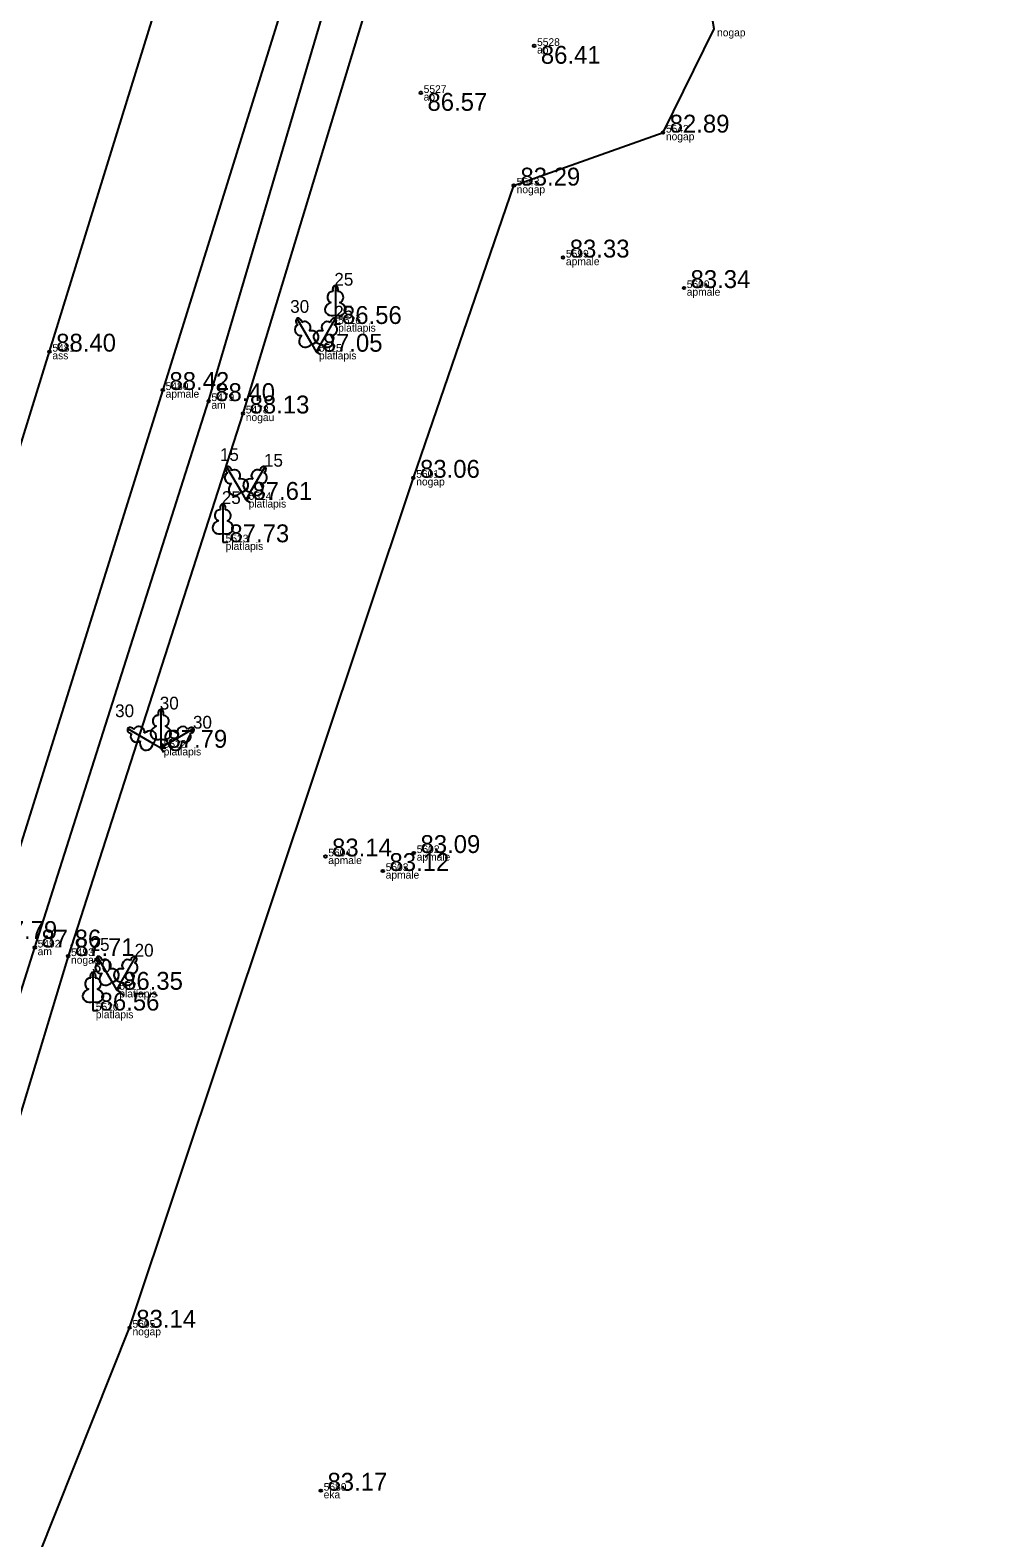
# Model space of a CAD drawing. Extents: x 614911 to 615803, y 262110 to 264311.
# Drawn here: x 615597 to 615634.5, y 262876.1 to 262935.1 of the extents above; entities that cross this region are included whole.
import ezdxf

# ---------------------------------------------------------------- set-up
doc = ezdxf.new("R2010")
doc.units = 0
for name, color, linetype in [('Level 1', 7, 'Continuous'), ('Level 31', 7, 'Continuous'), ('Level 37', 7, 'Continuous'), ('Level 53', 7, 'Continuous'), ('Level 54', 7, 'Continuous'), ('Level 57', 7, 'Continuous'), ('Level 58', 7, 'Continuous')]:
    doc.layers.add(name, color=color, linetype=linetype)

msp = doc.modelspace()

# ---------------------------------------------------------------- linework, layer by layer
at = {"layer": 'Level 1'}
for p, q in [((615608.989, 262923.95), (615608.989, 262923.603)), ((615608.989, 262923.603), (615609.189, 262923.603)), ((615608.062, 262922.817), (615608.235, 262922.516)), ((615608.408, 262922.817), (615608.235, 262922.516)), ((615608.235, 262922.516), (615608.408, 262922.616)), ((615608.235, 262922.516), (615608.408, 262922.416)), ((615605.308, 262917.015), (615605.481, 262916.714)), ((615605.654, 262917.015), (615605.481, 262916.714)), ((615605.481, 262916.714), (615605.654, 262916.814)), ((615605.481, 262916.714), (615605.654, 262916.614)), ((615604.58, 262915.399), (615604.58, 262915.052)), ((615604.58, 262915.052), (615604.78, 262915.052)), ((615601.85, 262907.176), (615602.151, 262907.003)), ((615602.151, 262907.35), (615602.151, 262907.003)), ((615602.151, 262907.003), (615602.251, 262907.176)), ((615602.452, 262907.176), (615602.151, 262907.003)), ((615602.151, 262907.003), (615602.351, 262907.003)), ((615602.151, 262907.003), (615602.251, 262906.83)), ((615600.242, 262897.825), (615600.415, 262897.524)), ((615600.588, 262897.825), (615600.415, 262897.524)), ((615600.415, 262897.524), (615600.588, 262897.624)), ((615600.415, 262897.524), (615600.588, 262897.424)), ((615599.495, 262897.056), (615599.495, 262896.709)), ((615599.495, 262896.709), (615599.695, 262896.709))]:
    msp.add_line(p, q, dxfattribs=at)
for points in [[(615608.989, 262925.103), (615608.989, 262923.95)], [(615609.079, 262924.871), (615609.078, 262924.872)], [(615607.485, 262923.815), (615608.062, 262922.817)], [(615607.679, 262923.659), (615607.677, 262923.659)], [(615608.985, 262923.815), (615608.408, 262922.817)], [(615608.946, 262923.569), (615608.946, 262923.57)], [(615604.731, 262918.013), (615605.308, 262917.015)], [(615604.925, 262917.857), (615604.923, 262917.857)], [(615606.231, 262918.013), (615605.654, 262917.015)], [(615606.192, 262917.767), (615606.192, 262917.768)], [(615604.58, 262916.552), (615604.58, 262915.399)], [(615604.67, 262916.32), (615604.669, 262916.321)], [(615602.151, 262908.503), (615602.151, 262907.35)], [(615602.241, 262908.271), (615602.24, 262908.272)], [(615600.852, 262907.753), (615601.85, 262907.176)], [(615601.098, 262907.714), (615601.097, 262907.714)], [(615603.45, 262907.753), (615602.452, 262907.176)], [(615603.294, 262907.559), (615603.294, 262907.561)], [(615599.665, 262898.823), (615600.242, 262897.825)], [(615599.859, 262898.667), (615599.857, 262898.667)], [(615601.165, 262898.823), (615600.588, 262897.825)], [(615599.495, 262898.209), (615599.495, 262897.056)], [(615601.126, 262898.577), (615601.126, 262898.578)], [(615599.585, 262897.977), (615599.584, 262897.978)]]:
    msp.add_lwpolyline(points, dxfattribs=at)
for centre, major_axis, ratio, start_param, end_param in [((615608.861, 262924.658), (-0.039, -0.212), 0.861323, 3.141593, 6.283185), ((615608.989, 262924.953), (0, -0.15), 0.707107, 3.14537, 5.287485), ((615608.989, 262924.953), (0, -0.15), 0.707107, 0.995701, 3.137816), ((615609.117, 262924.658), (0.039, -0.212), 0.861323, 0, 3.141593), ((615608.899, 262924.196), (0.307, 0.095), 0.814445, 1.570796, 4.752015), ((615609.079, 262924.196), (-0.307, 0.095), 0.814445, 1.531171, 4.712389), ((615607.596, 262923.366), (0.073, -0.203), 0.861323, 3.141593, 6.283185), ((615607.56, 262923.685), (0.075, -0.13), 0.707107, 3.14537, 5.287485), ((615607.56, 262923.685), (0.075, -0.13), 0.707107, 0.995701, 3.137816), ((615607.819, 262923.494), (0.14, -0.165), 0.861323, 0, 3.141593), ((615608.651, 262923.494), (-0.14, -0.165), 0.861323, 3.141593, 6.283185), ((615608.91, 262923.685), (-0.075, -0.13), 0.707107, 3.14537, 5.287485), ((615608.874, 262923.366), (-0.073, -0.203), 0.861323, 0, 3.141593), ((615608.91, 262923.685), (-0.075, -0.13), 0.707107, 0.995701, 3.137816), ((615607.861, 262922.985), (0.218, 0.236), 0.814445, 1.570796, 4.752015), ((615608.016, 262923.074), (-0.313, -0.071), 0.814445, 1.531171, 4.712389), ((615608.454, 262923.074), (0.313, -0.071), 0.814445, 1.570796, 4.752015), ((615608.609, 262922.985), (-0.218, 0.236), 0.814445, 1.531171, 4.712389), ((615604.842, 262917.564), (0.073, -0.203), 0.861323, 3.141593, 6.283185), ((615604.806, 262917.883), (0.075, -0.13), 0.707107, 3.14537, 5.287485), ((615604.806, 262917.883), (0.075, -0.13), 0.707107, 0.995701, 3.137816), ((615605.065, 262917.692), (0.14, -0.165), 0.861323, 0, 3.141593), ((615605.262, 262917.272), (-0.313, -0.071), 0.814445, 1.531171, 4.712389), ((615605.7, 262917.272), (0.313, -0.071), 0.814445, 1.570796, 4.752015), ((615605.897, 262917.692), (-0.14, -0.165), 0.861323, 3.141593, 6.283185), ((615606.156, 262917.883), (-0.075, -0.13), 0.707107, 3.14537, 5.287485), ((615606.12, 262917.564), (-0.073, -0.203), 0.861323, 0, 3.141593), ((615606.156, 262917.883), (-0.075, -0.13), 0.707107, 0.995701, 3.137816), ((615605.107, 262917.183), (0.218, 0.236), 0.814445, 1.570796, 4.752015), ((615605.855, 262917.183), (-0.218, 0.236), 0.814445, 1.531171, 4.712389), ((615604.452, 262916.107), (-0.039, -0.212), 0.861323, 3.141593, 6.283185), ((615604.58, 262916.402), (0, -0.15), 0.707107, 3.14537, 5.287485), ((615604.58, 262916.402), (0, -0.15), 0.707107, 0.995701, 3.137816), ((615604.708, 262916.107), (0.039, -0.212), 0.861323, 0, 3.141593), ((615604.49, 262915.645), (0.307, 0.095), 0.814445, 1.570796, 4.752015), ((615604.67, 262915.645), (-0.307, 0.095), 0.814445, 1.531171, 4.712389), ((615602.023, 262908.058), (-0.039, -0.212), 0.861323, 3.141593, 6.283185), ((615602.151, 262908.353), (0, -0.15), 0.707107, 3.14537, 5.287485), ((615602.151, 262908.353), (0, -0.15), 0.707107, 0.995701, 3.137816), ((615602.279, 262908.058), (0.039, -0.212), 0.861323, 0, 3.141593), ((615600.982, 262907.678), (0.13, -0.075), 0.707107, 3.14537, 5.287485), ((615600.982, 262907.678), (0.13, -0.075), 0.707107, 0.995701, 3.137816), ((615601.173, 262907.419), (0.165, -0.14), 0.861323, 3.141593, 6.283185), ((615601.301, 262907.642), (0.203, -0.073), 0.861323, 0, 3.141593), ((615601.682, 262907.377), (-0.236, -0.218), 0.814445, 1.531171, 4.712389), ((615602.061, 262907.596), (0.307, 0.095), 0.814445, 1.570796, 4.752015), ((615602.241, 262907.596), (-0.307, 0.095), 0.814445, 1.531171, 4.712389), ((615602.62, 262907.377), (0.236, -0.218), 0.814445, 1.570796, 4.752015), ((615603.001, 262907.642), (-0.203, -0.073), 0.861323, 3.141593, 6.283185), ((615603.129, 262907.419), (-0.165, -0.14), 0.861323, 0, 3.141593), ((615603.32, 262907.678), (-0.13, -0.075), 0.707107, 3.14537, 5.287485), ((615603.32, 262907.678), (-0.13, -0.075), 0.707107, 0.995701, 3.137816), ((615601.593, 262907.222), (0.071, 0.313), 0.814445, 1.570796, 4.752015), ((615602.709, 262907.222), (-0.071, 0.313), 0.814445, 1.531171, 4.712389), ((615599.74, 262898.693), (0.075, -0.13), 0.707107, 3.14537, 5.287485), ((615599.74, 262898.693), (0.075, -0.13), 0.707107, 0.995701, 3.137816), ((615599.999, 262898.502), (0.14, -0.165), 0.861323, 0, 3.141593), ((615600.831, 262898.502), (-0.14, -0.165), 0.861323, 3.141593, 6.283185), ((615601.09, 262898.693), (-0.075, -0.13), 0.707107, 3.14537, 5.287485), ((615601.09, 262898.693), (-0.075, -0.13), 0.707107, 0.995701, 3.137816), ((615599.495, 262898.059), (0, -0.15), 0.707107, 3.14537, 5.287485), ((615599.495, 262898.059), (0, -0.15), 0.707107, 0.995701, 3.137816), ((615599.776, 262898.374), (0.073, -0.203), 0.861323, 3.141593, 6.283185), ((615600.041, 262897.993), (0.218, 0.236), 0.814445, 1.570796, 4.752015), ((615600.196, 262898.082), (-0.313, -0.071), 0.814445, 1.531171, 4.712389), ((615600.634, 262898.082), (0.313, -0.071), 0.814445, 1.570796, 4.752015), ((615600.789, 262897.993), (-0.218, 0.236), 0.814445, 1.531171, 4.712389), ((615601.054, 262898.374), (-0.073, -0.203), 0.861323, 0, 3.141593), ((615599.405, 262897.302), (0.307, 0.095), 0.814445, 1.570796, 4.752015), ((615599.367, 262897.764), (-0.039, -0.212), 0.861323, 3.141593, 6.283185), ((615599.585, 262897.302), (-0.307, 0.095), 0.814445, 1.531171, 4.712389), ((615599.623, 262897.764), (0.039, -0.212), 0.861323, 0, 3.141593)]:
    msp.add_ellipse(centre, major_axis=major_axis, ratio=ratio, start_param=start_param, end_param=end_param, dxfattribs=at)
at = {"layer": 'Level 31'}
for points in [[(615632.734, 262974.874), (615627.762, 262975.783), (615624.583, 262974.081), (615622.329, 262970.726), (615619.288, 262963.641), (615611.976, 262941.852), (615605.37, 262920.098), (615598.524, 262898.844), (615592.115, 262877.692), (615586.071, 262858.355), (615583.42, 262849.533), (615582.048, 262845.554), (615581.571, 262838.931), (615579.909, 262826.022), (615579.783, 262825.588), (615576.605, 262812.081)], [(615581.33, 262813.385), (615587.235, 262840.341), (615585.874, 262843.893), (615588.538, 262850.225), (615593.068, 262864.597), (615600.932, 262884.287), (615612.047, 262917.578), (615615.98, 262929.024), (615621.827, 262931.099), (615623.831, 262935.169), (615622.903, 262940.536), (615628.682, 262961.888), (615634.511, 262966.199), (615634.511, 262966.199)]]:
    msp.add_lwpolyline(points, dxfattribs=at)
at = {"layer": 'Level 37'}
for points in [[(615552.83, 262775.419), (615557.688, 262792.217), (615564.381, 262810.929), (615568.874, 262829.598), (615578.474, 262860.105), (615584.765, 262880.506), (615591.133, 262901.009), (615597.793, 262922.52), (615604.506, 262944.221), (615611.821, 262967.016), (615619.311, 262990.31), (615624.144, 263005.661), (615628.856, 263023.992)], [(615633.153, 262995.478), (615630.105, 262994.778), (615627.249, 262993.097), (615624.165, 262989.775), (615623.012, 262986.721), (615615.941, 262964.659), (615608.941, 262942.572), (615602.23, 262921.018), (615595.493, 262899.514), (615589.041, 262878.574), (615583.023, 262859.136), (615579.804, 262848.845), (615577.579, 262826.156), (615572.51, 262808.384), (615566.84, 262788.492), (615562.353, 262772.755), (615562.228, 262772.268), (615562.322, 262770.686), (615563.546, 262768.507), (615565.703, 262767.319), (615569.868, 262766.432), (615584.992, 262762.796)], [(615576.19, 262811.993), (615576.066, 262812.682), (615575.818, 262813.59), (615579.291, 262825.832), (615581.523, 262848.494), (615584.551, 262858.603), (615590.575, 262878.181), (615597.215, 262899.18), (615604.023, 262920.582), (615610.418, 262942.235), (615617.538, 262964.274), (615623.159, 262980.563)]]:
    msp.add_lwpolyline(points, dxfattribs=at)
at = {"layer": 'Level 57'}
for centre in [(615616.78, 262934.495), (615612.338, 262932.653), (615621.827, 262931.099), (615615.98, 262929.024), (615617.911, 262926.205), (615622.644, 262925.01), (615597.793, 262922.52), (615602.23, 262921.018), (615604.023, 262920.582), (615605.37, 262920.098), (615612.047, 262917.578), (615608.601, 262902.748), (615612.065, 262902.881), (615610.85, 262902.177), (615597.215, 262899.18), (615598.524, 262898.844), (615600.932, 262884.287), (615608.421, 262877.903)]:
    msp.add_circle(centre, 0.05, dxfattribs=at)
at = {"layer": 'Level 58'}
for centre in [(615616.78, 262934.495), (615612.338, 262932.653), (615621.827, 262931.099), (615615.98, 262929.024), (615617.911, 262926.205), (615622.644, 262925.01), (615597.793, 262922.52), (615602.23, 262921.018), (615604.023, 262920.582), (615605.37, 262920.098), (615612.047, 262917.578), (615608.601, 262902.748), (615612.065, 262902.881), (615610.85, 262902.177), (615597.215, 262899.18), (615598.524, 262898.844), (615600.932, 262884.287), (615608.421, 262877.903)]:
    msp.add_circle(centre, 0.05, dxfattribs=at)

# ---------------------------------------------------------------- texts
at = {"layer": 'Level 1'}
for s, p in [(' 25', (615608.764, 262925.103)), (' 30', (615607.035, 262924.04)), (' 25', (615608.76, 262923.815)), (' 15', (615604.281, 262918.238)), (' 15', (615606.006, 262918.013)), (' 25', (615604.355, 262916.552)), (' 30', (615600.177, 262908.203)), (' 30', (615601.926, 262908.503)), (' 30', (615603.225, 262907.753)), (' 25', (615599.215, 262899.048)), (' 20', (615600.94, 262898.823)), (' 30', (615599.27, 262898.209))]:
    msp.add_text(s, height=0.5, dxfattribs=at).set_placement(p)
at = {"layer": 'Level 53'}
for s, p in [(' nogap', (615623.831, 262934.869)), (' ap', (615616.78, 262934.195)), (' ap', (615612.338, 262932.353)), (' nogap', (615621.827, 262930.799)), (' nogap', (615615.98, 262928.724)), (' apmale', (615617.911, 262925.905)), (' apmale', (615622.644, 262924.71)), (' platlapis', (615608.989, 262923.303)), (' ass', (615597.793, 262922.22)), (' platlapis', (615608.235, 262922.216)), (' apmale', (615602.23, 262920.718)), (' am', (615604.023, 262920.282)), (' nogau', (615605.37, 262919.798)), (' nogap', (615612.047, 262917.278)), (' platlapis', (615605.481, 262916.414)), (' platlapis', (615604.58, 262914.752)), (' platlapis', (615602.151, 262906.703)), (' apmale', (615608.601, 262902.448)), (' apmale', (615612.065, 262902.581)), (' apmale', (615610.85, 262901.877)), (' am', (615597.215, 262898.88)), (' nogau', (615598.524, 262898.544)), (' platlapis', (615600.415, 262897.224)), (' platlapis', (615599.495, 262896.409)), (' nogap', (615600.932, 262883.987)), (' eka', (615608.421, 262877.603))]:
    msp.add_text(s, height=0.3, dxfattribs=at).set_placement(p)
at = {"layer": 'Level 54'}
for s, p in [(' 5528', (615616.78, 262934.495)), (' 5527', (615612.338, 262932.653)), (' 5542', (615621.827, 262931.099)), (' 5543', (615615.98, 262929.024)), (' 5599', (615617.911, 262926.205)), (' 5600', (615622.644, 262925.01)), (' 5526', (615608.989, 262923.603)), (' 5481', (615597.793, 262922.52)), (' 5525', (615608.235, 262922.516)), (' 5480', (615602.23, 262921.018)), (' 5479', (615604.023, 262920.582)), (' 5478', (615605.37, 262920.098)), (' 5601', (615612.047, 262917.578)), (' 5524', (615605.481, 262916.714)), (' 5523', (615604.58, 262915.052)), (' 5522', (615602.151, 262907.003)), (' 5604', (615608.601, 262902.748)), (' 5602', (615612.065, 262902.881)), (' 5603', (615610.85, 262902.177)), (' 5492', (615597.215, 262899.18)), (' 5493', (615598.524, 262898.844)), (' 5521', (615600.415, 262897.524)), (' 5520', (615599.495, 262896.709)), (' 5605', (615600.932, 262884.287)), (' 5680', (615608.421, 262877.903))]:
    msp.add_text(s, height=0.3, dxfattribs=at).set_placement(p)
at = {"layer": 'Level 58'}
for s, p in [(' 86.41', (615616.78, 262933.795)), (' 86.57', (615612.338, 262931.953)), (' 82.89', (615621.827, 262931.099)), (' 83.29', (615615.98, 262929.024)), (' 83.33', (615617.911, 262926.205)), (' 83.34', (615622.644, 262925.01)), (' 86.56', (615608.989, 262923.603)), (' 88.40', (615597.793, 262922.52)), (' 87.05', (615608.235, 262922.516)), (' 88.42', (615602.23, 262921.018)), (' 88.40', (615604.023, 262920.582)), (' 88.13', (615605.37, 262920.098)), (' 83.06', (615612.047, 262917.578)), (' 87.61', (615605.481, 262916.714)), (' 87.73', (615604.58, 262915.052)), (' 87.79', (615602.151, 262907.003)), (' 83.14', (615608.601, 262902.748)), (' 83.09', (615612.065, 262902.881)), (' 83.12', (615610.85, 262902.177)), (' 87.79', (615595.493, 262899.514)), (' 87.86', (615597.215, 262899.18)), (' 87.71', (615598.524, 262898.844)), (' 86.35', (615600.415, 262897.524)), (' 86.56', (615599.495, 262896.709)), (' 83.14', (615600.932, 262884.287)), (' 83.17', (615608.421, 262877.903))]:
    msp.add_text(s, height=0.7, dxfattribs=at).set_placement(p)

doc.saveas('drawing.dxf')
